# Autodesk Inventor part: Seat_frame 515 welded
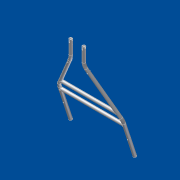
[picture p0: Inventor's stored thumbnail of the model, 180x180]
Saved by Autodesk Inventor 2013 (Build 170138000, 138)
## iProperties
Shininess: 69.0
Length Units: 11269
Angle Units: 11279
Time Units: 11290
Mass Units: 11283
Length Display Precision: 3
Angle Display Precision: 2
Created: 2001-05
Part Number: Seat_frame 515 welded
Material: Standard
Document SubType Name: Modellieren
Designer: dl
Density: 1 g/cm^3
Density: 0.0
Volumn: 0.0
Area: 0.0
PropertySet Name: Model Information
Control State: 0
Master: False
Checked Out: False
Author: dl
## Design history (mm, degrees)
derived "Seat_frame_assembly 515 wide.iam"
  feature "Joint.ipt:1" dims "d19" = 10
  feature "Joint.ipt:2" dims "d19" = 10
  feature "Seat_frame_half_right 515.ipt:1" dims "d19" = 10
  feature "Seat_frame_half_left 515.ipt:1" dims "d19" = 10
  feature "Seam_ipart [d2=515 mm].ipt:1" dims "d19" = 10
  feature "Cross_girder 515.ipt:1" dims "d19" = 10
sketch "Sketch1"
  geometry: L1 (9.5, 0)-(-9.5, 0) reference; L2 (0, -168.036)-(0, 956.788) reference; L3 (-502.5, 0)-(-527.5, 0) reference; L4 (-515, -168.036)-(-515, 956.788) reference; C1 r 2.5 at (0, 10); C2 r 2.5 at (-515, 10)
  constraints: 2 centre point
  dimensions: "d2" = 5 diameter of C1; "d3" = 10 distance from line of L1 C1.centre; "d4" = 0 distance from line of L2 C1.centre; "d13" = 0 distance from line of L4 C2.centre; "d14" = 10 distance from line of L3 C2.centre (= d3); "d15" = 5 diameter of C2 (= d2)
extrude "Extrusion1" cut sketch "Sketch1" stored distance "d5" = 10; taper "d6" = 0 deg
sketch "Sketch2"
  geometry: L1 (-750.721, -101.514)-(-74.657, 1069.462) reference; L2 (235.721, -101.514)-(-440.343, 1069.462) reference; C1 r 3.5 at (-335.5, 617.669); C2 r 3.5 at (-179.5, 617.669)
  constraints: 2 centre point, 2 point on line
  dimensions: "d7" = 7 diameter of C1; "d8" = 7 diameter of C2 (= d7); "d9" = 156 distance of C2.centre C1.centre; "d10" = 0 vertical distance of C2.centre C1.centre
extrude "Extrusion2" cut sketch "Sketch2" stored distance "d11" = 25; taper "d12" = 0 deg
body "Solid1"
workaxis "Work Axis1"
workaxis "Work Axis2"
workplane "Work Plane1"
workaxis "Work Axis3"
workaxis "Work Axis4"
workplane "Work Plane2"
fillet "Fillet1" dims "d17" = 3
other parameters: "d16" = -48.425
